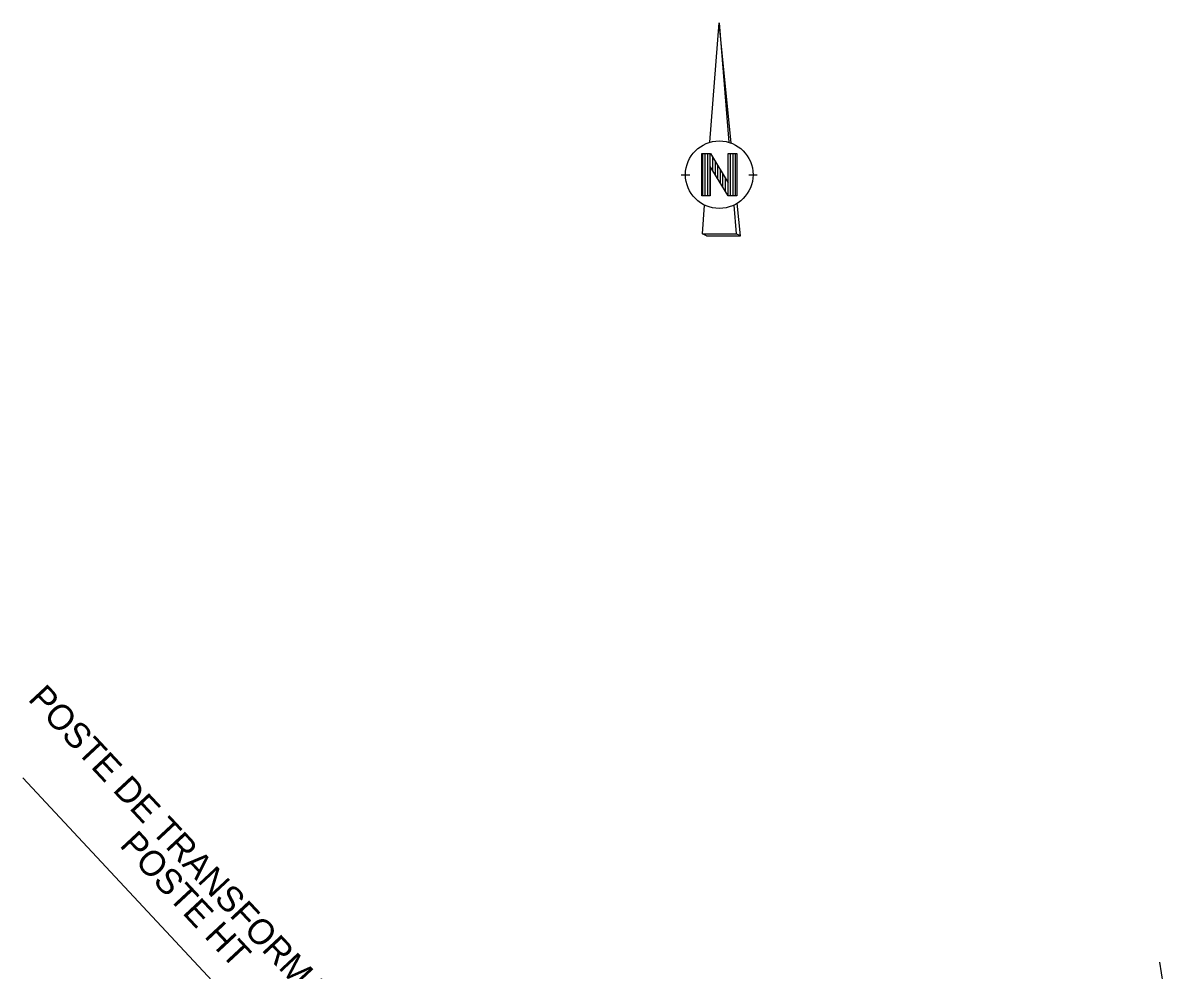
# Model space of a CAD drawing. Extents: x 703432 to 707394, y 7057985 to 7059523.
# Drawn here: x 703864.5 to 703999.6, y 7058552.7 to 7058665 of the extents above; entities that cross this region are included whole.
import ezdxf

# ---------------------------------------------------------------- set-up
doc = ezdxf.new("R2010")
doc.units = 0
for name, color, linetype in [('DH_NORD', 7, 'Continuous'), ('R_ELEC_BT_60HZ_LIAISON_CL_B', 7, 'Continuous'), ('VOIRIE_ROUTE', 7, 'Continuous')]:
    doc.layers.add(name, color=color, linetype=linetype)

msp = doc.modelspace()

# ---------------------------------------------------------------- linework, layer by layer
at = {"layer": 'DH_NORD'}
for p, q in [((703945.89, 7058650.85), (703947.02, 7058665.01)), ((703947.02, 7058665.01), (703948.15, 7058650.85)), ((703948.43, 7058650.75), (703947.02, 7058665.01)), ((703944.96, 7058649.51), (703945.97, 7058649.51)), ((703944.96, 7058644.5), (703944.96, 7058649.51)), ((703945.06, 7058644.5), (703945.06, 7058649.51)), ((703945.36, 7058644.5), (703945.36, 7058649.51)), ((703945.66, 7058644.5), (703945.66, 7058649.51)), ((703945.96, 7058644.5), (703945.96, 7058649.51)), ((703945.97, 7058649.51), (703948.09, 7058646.04)), ((703946.26, 7058647.49), (703946.26, 7058649.04)), ((703948.09, 7058646.04), (703948.09, 7058649.51)), ((703948.09, 7058649.51), (703949.09, 7058649.51)), ((703948.36, 7058644.5), (703948.36, 7058649.51)), ((703948.66, 7058644.5), (703948.66, 7058649.51)), ((703948.96, 7058644.5), (703948.96, 7058649.51)), ((703949.09, 7058649.51), (703949.09, 7058644.5)), ((703948.08, 7058644.5), (703945.96, 7058647.97)), ((703945.96, 7058647.97), (703945.96, 7058644.5)), ((703946.56, 7058647), (703946.56, 7058648.55)), ((703946.86, 7058646.5), (703946.86, 7058648.06)), ((703942.52, 7058647.01), (703943.52, 7058647.01)), ((703947.16, 7058646.01), (703947.16, 7058647.57)), ((703947.46, 7058645.52), (703947.46, 7058647.07)), ((703947.76, 7058645.03), (703947.76, 7058646.58)), ((703950.52, 7058647.01), (703951.52, 7058647.01)), ((703948.06, 7058644.54), (703948.06, 7058646.09)), ((703945.96, 7058644.5), (703944.96, 7058644.5)), ((703949.09, 7058644.5), (703948.08, 7058644.5)), ((703949.52, 7058639.76), (703949.14, 7058643.62)), ((703945.02, 7058640.01), (703945.29, 7058643.4)), ((703948.75, 7058643.4), (703949.02, 7058640.01)), ((703945.02, 7058640.01), (703949.02, 7058640.01)), ((703945.52, 7058639.76), (703945.02, 7058640.01)), ((703945.52, 7058639.76), (703949.52, 7058639.76)), ((703949.52, 7058639.76), (703949.02, 7058640.01))]:
    msp.add_line(p, q, dxfattribs=at)
msp.add_circle((703947.02, 7058647.01), 4, dxfattribs=at)
at = {"layer": 'R_ELEC_BT_60HZ_LIAISON_CL_B'}
msp.add_line((703896.95, 7058540.81), (703864.53, 7058575.54), dxfattribs=at)
at = {"layer": 'VOIRIE_ROUTE'}
msp.add_lwpolyline([(703999.6, 7058551.16), (703999.21, 7058553.7)], dxfattribs=at)

# ---------------------------------------------------------------- texts
at = {"layer": 'R_ELEC_BT_60HZ_LIAISON_CL_B'}
for s, p in [('POSTE DE TRANSFORMATION', (703865.04, 7058584.79)), ('POSTE HT', (703875.89, 7058567.48))]:
    msp.add_text(s, height=3, rotation=313.0213, dxfattribs=at).set_placement(p)

doc.saveas('drawing.dxf')
